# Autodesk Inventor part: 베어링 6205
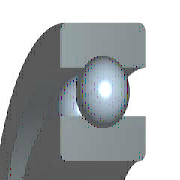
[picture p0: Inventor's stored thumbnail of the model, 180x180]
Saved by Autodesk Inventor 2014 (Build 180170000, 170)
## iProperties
IsCustomPart: 1
Company: 한국ATC센터
Created: 2014-10
Part Number: 베어링 6205
Material: 강, 연강
Description: 깊은 그루브 볼 베어링
Document SubType Name: Modeling
Standard: KS B 2023
Designer: 한국ATC센터
Standards Organization: KS
Language: ko-KR
Size Designation: 6205 - 25 x 52 x 15
Categories: <MemberInstance><Categories><Category DisplayName="샤프트 부품" InternalName="7f7aeb1f-a693-4053-b835-cee3144e0d98" Mnemonic="SHFT"><Category DisplayName="베어링" Inter
Density: 7.86 g/cm^3
Mass: 129.543 g
Surface Area: 107.326 cm^2
Volume: 16.4813 cm^3
Appearance: 강철
Author: KYOUNG IL JANG
Revision Number: 1
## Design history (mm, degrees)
sketch "스케치" dims "d0" = 7.02 (= -0.26 x WD + 0.26 x BD)
  geometry: L1 (3.99, 19.25)-(11.01, 19.25); L2 (7.5, 19.25)-(7.5, 15.74); L3 (7.5, 19.25)-(7.5, 22.76); L4 (4.892, 16.901)-(0, 16.901); L5 (0, 12.5)-(15, 12.5); L6 (4.892, 21.599)-(0, 21.599); L7 (0, 26)-(15, 26); L8 (15, 12.5)-(15, 16.901); L9 (10.108, 16.901)-(15, 16.901); L10 (10.108, 21.599)-(15, 21.599); L11 (15, 26)-(15, 21.599); L12 (-1.4, 0)-(8.4, 0) reference; L13 (0, -0.3)-(0, 5.3) reference
  constraints: 22 end point, 4 point on line, 2 collinear, 2 perpendicular, 2 symmetric about line, 1 midpoint, 1 parallel, 14 other
  dimensions: "d9" = 25 diameter of L5 L12 (= WD); "d11" = 52 diameter of L7 L12 (= BD); "d12" = 15 distance between parallel lines of L8 L13 (= KB); "d13" = 33.802 diameter of L9 L12 (= 0.326 x BD + 0.674 x WD)
revolve "본체" stored, may be unused: angle "d6" = 90 deg
revolve "볼" stored, may be unused: angle "d7" = 90 deg
pattern_circular "IDS_ARRAYBALL[SIMPL:T]" dims angle "d3" = 360 deg
body "Solid1"
fillet "모깎기1" dims "d1" = 1 (= KRS)
other parameters: "WD" = 25 [user parameter; used in 5 equation terms], "BD" = 52 [user parameter; used in 5 equation terms], "KB" = 15 [user parameter; used in 1 equation term], "KRS" = 1 [user parameter; used in 1 equation term], "d4" = 0, "d5" = 0, "d8" = 0, "d14" = 0, "d15" = 0, "BBA" = 0 [user parameter], "BC0" = 7800000 [user parameter], "BC" = 1.4e+07 [user parameter], "BR" = 26 (= 0.5 x BD) [user parameter], "WR" = 12.5 (= 0.5 x WD) [user parameter]
